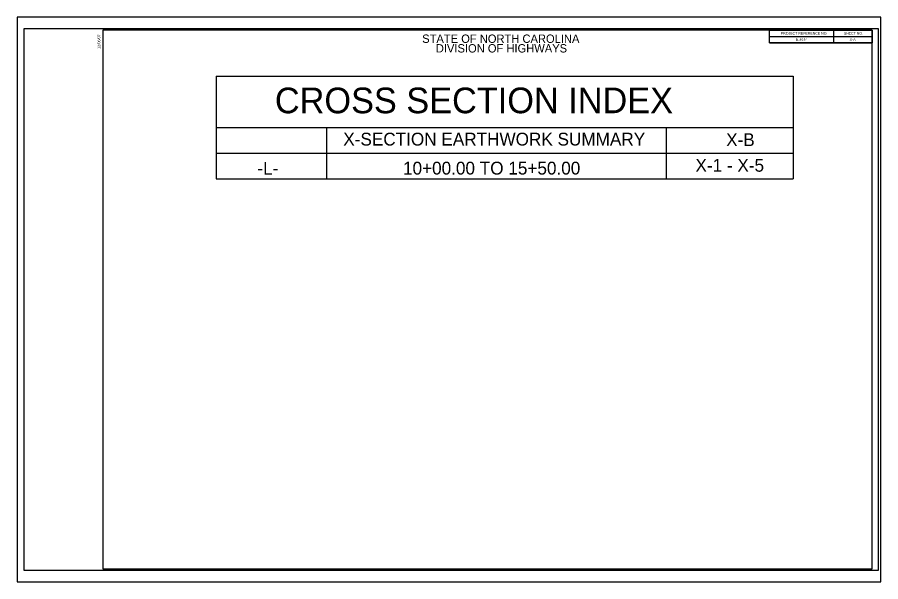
# Model space of a CAD drawing. Extents: x 573852.9 to 573886.5, y -53297.3 to -53275.3.
import ezdxf

# ---------------------------------------------------------------- set-up
doc = ezdxf.new("R2010")
doc.units = 0
for name, color, linetype in [('Sheet Cutting Line CELL', 7, 'Continuous'), ('Sheet Plot Border Inside CELL', 7, 'Continuous'), ('Sheet Plot Border Outside CELL', 7, 'Continuous'), ('Sheet Summary Combination CELL', 7, 'Continuous'), ('Sheet Summary Combination Grid CELL', 7, 'Continuous')]:
    doc.layers.add(name, color=color, linetype=linetype)

msp = doc.modelspace()

# ---------------------------------------------------------------- linework, layer by layer
at = {"layer": 'Sheet Cutting Line CELL'}
for p, q in [((573886.549, -53275.344), (573852.869, -53275.344)), ((573852.869, -53275.344), (573852.869, -53297.344)), ((573852.869, -53297.344), (573886.549, -53297.344))]:
    msp.add_line(p, q, dxfattribs=at)
at = {"layer": 'Sheet Plot Border Inside CELL'}
msp.add_lwpolyline([(573886.459, -53275.793), (573853.129, -53275.793), (573853.129, -53296.895), (573886.459, -53296.895)], close=True, dxfattribs=at)
at = {"layer": 'Sheet Plot Border Outside CELL'}
msp.add_lwpolyline([(573886.549, -53275.344), (573852.869, -53275.344), (573852.869, -53297.344), (573886.549, -53297.344)], close=True, dxfattribs=at)
at = {"layer": 'Sheet Summary Combination CELL'}
for p, q in [((573884.709, -53275.845), (573884.709, -53276.345)), ((573882.208, -53276.095), (573886.209, -53276.095)), ((573882.208, -53276.345), (573886.209, -53276.345)), ((573871.928, -53277.648), (573871.928, -53277.648)), ((573872.428, -53277.656), (573872.428, -53277.656)), ((573873.152, -53277.64), (573873.152, -53277.64)), ((573873.6, -53277.648), (573873.6, -53277.648))]:
    msp.add_line(p, q, dxfattribs=at)
for points in [[(573886.209, -53275.844), (573856.209, -53275.844), (573856.209, -53296.844), (573886.209, -53296.844)], [(573882.208, -53275.844), (573886.209, -53275.844), (573886.209, -53276.345), (573882.208, -53276.345)]]:
    msp.add_lwpolyline(points, close=True, dxfattribs=at)
at = {"layer": 'Sheet Summary Combination Grid CELL'}
for p, q in [((573860.628, -53277.644), (573883.136, -53277.644)), ((573860.628, -53277.644), (573860.628, -53281.644)), ((573883.136, -53277.644), (573883.136, -53281.644)), ((573860.628, -53279.644), (573883.136, -53279.644)), ((573864.932, -53279.652), (573864.932, -53281.644)), ((573878.176, -53279.664), (573878.176, -53281.644)), ((573860.628, -53280.644), (573883.136, -53280.644)), ((573860.628, -53281.644), (573883.136, -53281.644))]:
    msp.add_line(p, q, dxfattribs=at)

# ---------------------------------------------------------------- texts
at = {"layer": 'Sheet Summary Combination CELL'}
for s, height, rotation, p in [('12/06/07', 0.105, 90, (573856.106, -53276.572)), ('CROSS SECTION INDEX', 1.00001, 0.0119, (573862.918, -53279.085)), ('-L-', 0.5, 0.0119, (573862.236, -53281.48)), ('10+00.00 TO 15+50.00', 0.5, 0.0119, (573867.916, -53281.474)), ('X-1 - X-5', 0.5, 0.0119, (573879.323, -53281.364))]:
    msp.add_text(s, height=height, rotation=rotation, dxfattribs=at).set_placement(p)
for s, height, p in [('STATE OF NORTH CAROLINA', 0.325, (573868.664, -53276.341)), ('PROJECT REFERENCE NO.', 0.1, (573882.652, -53276.018)), ('SHEET NO.', 0.1, (573885.115, -53276.02)), ('B-4944', 0.1, (573883.238, -53276.27)), ('X-A', 0.1, (573885.339, -53276.264)), ('DIVISION OF HIGHWAYS', 0.325, (573869.196, -53276.716)), ('X-SECTION EARTHWORK SUMMARY', 0.5, (573865.586, -53280.343)), ('X-B', 0.5, (573880.52, -53280.366))]:
    msp.add_text(s, height=height, dxfattribs=at).set_placement(p)

doc.saveas('drawing.dxf')
